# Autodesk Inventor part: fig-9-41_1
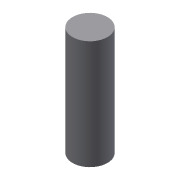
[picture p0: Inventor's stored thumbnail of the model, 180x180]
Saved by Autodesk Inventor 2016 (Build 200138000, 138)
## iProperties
Created: 2013-03
Part Number: fig-9-41_1
Material: Generic
Document SubType Name: Modeling
Designer: CADCIM
Density: 1 g/cm^3
Appearance: Default
Author: CADCIM
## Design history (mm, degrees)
sketch "Sketch1"
  geometry: C1 r 4 at (0, 0); 1 further point
  constraints: 1 centre point, 1 coincident
  dimensions: "d0" = 8 diameter of C1
extrude "Extrusion1" new body sketch "Sketch1" stored distance "d2" = 25; taper "d3" = 0 deg
body "Solid1"
